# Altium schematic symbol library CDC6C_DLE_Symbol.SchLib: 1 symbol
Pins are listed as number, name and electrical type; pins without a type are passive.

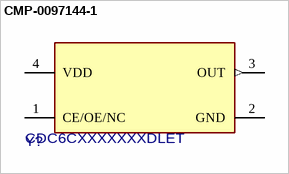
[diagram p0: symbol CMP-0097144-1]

## CMP-0097144-1
designator Y?, comment CDC6CXXXXXXXDLET
High-Performance BAW Oscillator; Manufacturer: Texas Instruments; SizeZ_mm: 1mm; Max Supply Voltage: 3.63V; Standoff Height: 0mm; Frequency Stability: 25ppm; Min Supply Voltage: 1.62V; TJmax_C: +130°C; AEC Qualified: No
footprint DLE0004A-MFG
pins: 1 CE/OE/NC, 2 GND (power), 3 OUT (out), 4 VDD (power)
